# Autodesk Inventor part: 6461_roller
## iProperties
Author: Ole Germer
Shininess: 64.0
Angle Display Precision: 2
Document Length Units: 11272
Document Angle Units: 11286
Document Time Units: 11279
Document Mass Units: 11290
Document Length Units Precision: 3
Document Angle Units Precision: 2
Compacted: True
PropertySet Name: _Private Model Information
Created: 2002-10
Part Number: 6461_roller
Material: ASTM A36 HRS
Document SubType Name: Modeling
Designer: Ole Germer
Control State: 0
Master: False
Checked Out: False
PropertySet Name: Design Tracking Control
Density: 0.0
Volumn: 0.0
Area: 0.0
PropertySet Name: Model Information
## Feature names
1. Revolution1
